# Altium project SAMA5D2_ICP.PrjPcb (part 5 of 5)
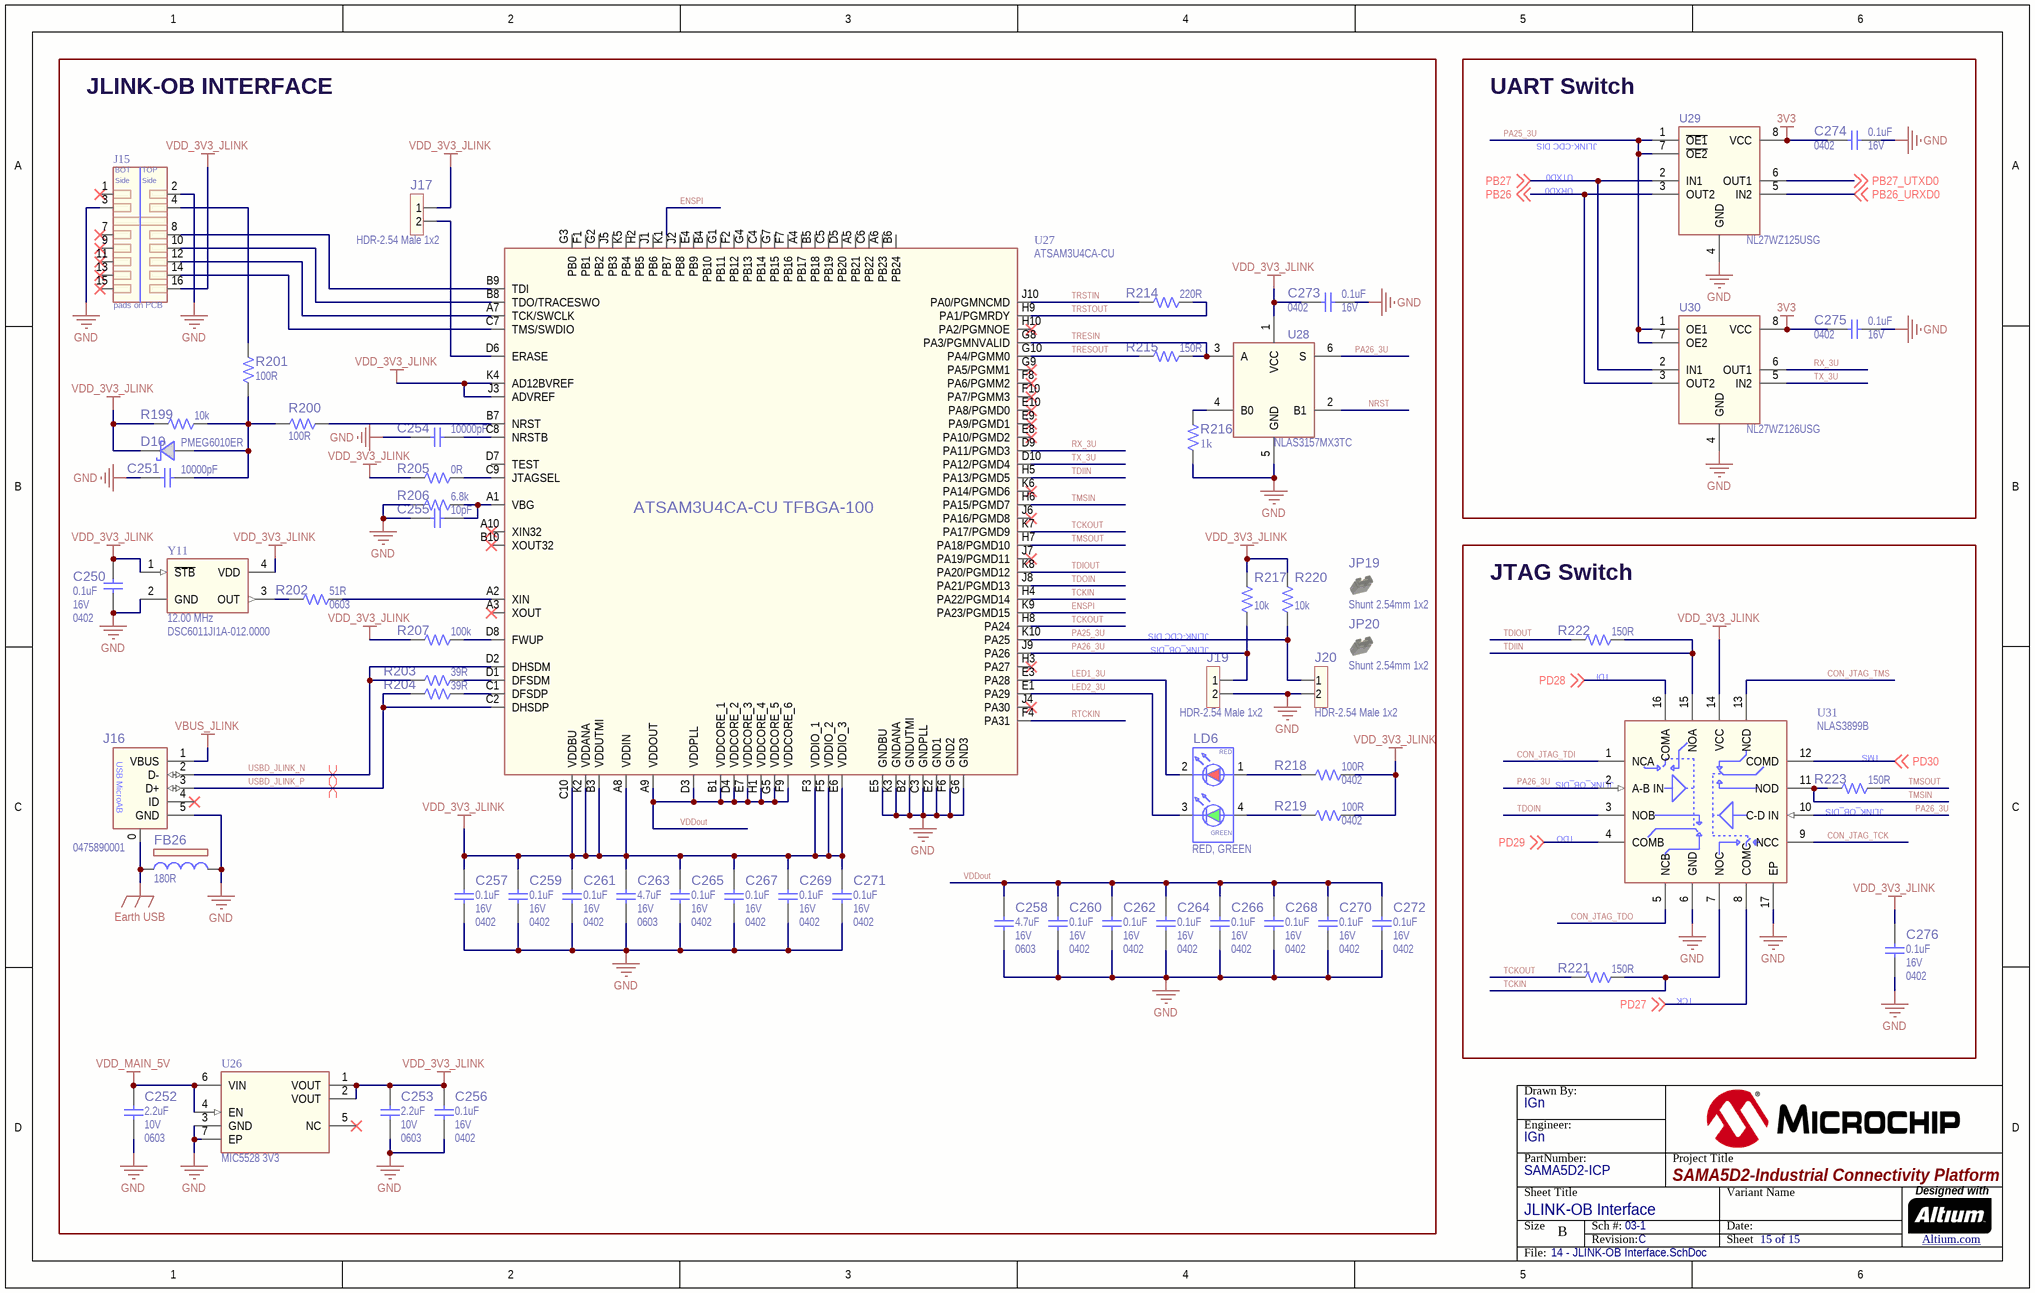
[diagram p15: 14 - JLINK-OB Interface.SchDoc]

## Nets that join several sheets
1V25: 01 - Power Supply (C16.1 L3.2 U2.25), 02 - Power Measurement (FB1.1 FB2.1 R18.1 R19.1), 08 - Ethernet switch (15 pins)
1V35: 01 - Power Supply (C14.1 L2.2 U2.16), 02 - Power Measurement (R17.1)
3V3: 01 - Power Supply (7 pins), 02 - Power Measurement (7 pins), 03 - SAMA5D2 - MPU (C52.2 R166.1 Y3.4), 05 - SAMA5D2 - PIOs (10 pins), 06 - USB (16 pins), 07 - USB HSIC to Gb Ethernet (31 pins), 08 - Ethernet switch (28 pins), 09 - EtherCAT interface (32 pins), 10 - CAN & WiFi BT (12 pins), 11 - On Board Memories (19 pins), 12 - Expansion connectors (R106.1 R229.1 R230.1 R231.1), 13 - User Command & Control (J18.1 R211.2 R212.2 R213.2), 14 - JLINK-OB Interface (C274.2 C275.2 U29.8 U30.8)
Earth USB: 06 - USB (FB14.2 J7.0 J8.0 J9.0), 14 - JLINK-OB Interface (FB26.1 J16.0)
GND: 01 - Power Supply (37 pins), 02 - Power Measurement (9 pins), 03 - SAMA5D2 - MPU (79 pins), 04 - SAMA5D2 - DDR (93 pins), 05 - SAMA5D2 - PIOs (C58.1 C59.1 U35.2 U36.2), 06 - USB (51 pins), 07 - USB HSIC to Gb Ethernet (37 pins), 08 - Ethernet switch (56 pins), 09 - EtherCAT interface (68 pins), 10 - CAN & WiFi BT (39 pins), 11 - On Board Memories (15 pins), 12 - Expansion connectors (11 pins), 13 - User Command & Control (20 pins), 14 - JLINK-OB Interface (50 pins)
VBUS_JLINK: 01 - Power Supply (C4.2 Q2.1 R11.1), 14 - JLINK-OB Interface (J16.1)
VDD_LED: 01 - Power Supply (C10.2 U2.21), 13 - User Command & Control (LD7.2)
VDD_MAIN_5V: 01 - Power Supply (20 pins), 02 - Power Measurement (C22.2 C24.2 U3.A4), 06 - USB (C144.1 C145.1 U16.7 U17.7), 10 - CAN & WiFi BT (7 pins), 12 - Expansion connectors (R236.1 R237.1 R238.1), 14 - JLINK-OB Interface (C252.2 U26.4 U26.6)
VDDANA: 02 - Power Measurement (FB8.2), 03 - SAMA5D2 - MPU (5 pins)
VDDAUDIOPLL: 02 - Power Measurement (L7.2), 03 - SAMA5D2 - MPU (C57.2 C61.2 U4.T3)
VDDBU: 01 - Power Supply (J2.1 R256.2), 03 - SAMA5D2 - MPU (C56.2 R75.1 U4.N7)
VDDCORE: 02 - Power Measurement (R18.2), 03 - SAMA5D2 - MPU (14 pins)
VDDFUSE: 01 - Power Supply (C9.2 U2.19), 03 - SAMA5D2 - MPU (C55.2 U4.M12)
VDDHSIC: 02 - Power Measurement (FB2.2), 03 - SAMA5D2 - MPU (C47.2 U4.R9)
VDDIODDR: 02 - Power Measurement (C23.2 C25.2 R17.2 R25.2), 03 - SAMA5D2 - MPU (15 pins), 04 - SAMA5D2 - DDR (81 pins)
VDDIOP0: 02 - Power Measurement (FB3.2), 03 - SAMA5D2 - MPU (C37.2 C41.2 U4.E6 U4.F7)
VDDIOP1: 02 - Power Measurement (FB4.2), 03 - SAMA5D2 - MPU (C46.2 C50.2 U4.N13 U4.R14)
VDDIOP2: 02 - Power Measurement (FB5.2), 03 - SAMA5D2 - MPU (C38.2 U4.F10)
VDDISC: 02 - Power Measurement (FB6.2), 03 - SAMA5D2 - MPU (C73.2 U4.F4)
VDDOSC: 02 - Power Measurement (L6.2), 03 - SAMA5D2 - MPU (C71.2 C72.2 U4.T7)
VDDPLLA: 02 - Power Measurement (L5.2), 03 - SAMA5D2 - MPU (C69.2 C70.2 U4.U4)
VDDSDHC: 02 - Power Measurement (FB9.2), 03 - SAMA5D2 - MPU (C66.2 U4.P11)
VDDUTMIC: 02 - Power Measurement (FB1.2), 03 - SAMA5D2 - MPU (C62.2 C65.2 U4.P7)
VDDUTMII: 02 - Power Measurement (FB7.2), 03 - SAMA5D2 - MPU (C64.2 U4.P8)
CON_JTAG_TCK: 13 - User Command & Control (J18.4 R212.1), 14 - JLINK-OB Interface (U31.9)
CON_JTAG_TDI: 13 - User Command & Control (J18.8 R213.1), 14 - JLINK-OB Interface (U31.1)
CON_JTAG_TDO: 13 - User Command & Control (J18.6), 14 - JLINK-OB Interface (U31.5)
CON_JTAG_TMS: 13 - User Command & Control (J18.2 R211.1), 14 - JLINK-OB Interface (U31.13)
DDR_REF: 02 - Power Measurement (C25.1 C26.2 R25.1 R26.2), 04 - SAMA5D2 - DDR (11 pins)
DIS_BOOT: 11 - On Board Memories (R80.1 U5.1), 13 - User Command & Control (R251.1)
HHSA_n: 03 - SAMA5D2 - MPU (U4.R8), 06 - USB (J9.2)
HHSA_p: 03 - SAMA5D2 - MPU (U4.T8), 06 - USB (J9.3)
HHSB_n: 03 - SAMA5D2 - MPU (U4.U9), 06 - USB (U15.30)
HHSB_p: 03 - SAMA5D2 - MPU (U4.U8), 06 - USB (U15.31)
HSIC_DATA: 03 - SAMA5D2 - MPU (U4.T9), 07 - USB HSIC to Gb Ethernet (U19.38)
HSIC_STROBE: 03 - SAMA5D2 - MPU (U4.U10), 07 - USB HSIC to Gb Ethernet (U19.35)
NRST: 01 - Power Supply (R2.1 U2.2), 03 - SAMA5D2 - MPU (U4.U2), 06 - USB (U12.2), 07 - USB HSIC to Gb Ethernet (U18.2), 08 - Ethernet switch (U20.2), 09 - EtherCAT interface (U22.2), 13 - User Command & Control (R210.2 R250.1), 14 - JLINK-OB Interface (U28.2)
NSTART: 01 - Power Supply (C2.2 U2.24), 13 - User Command & Control (R252.1)
PA0: 05 - SAMA5D2 - PIOs (U4.U11), 12 - Expansion connectors (J5.5)
PA1: 05 - SAMA5D2 - PIOs (U4.P10), 12 - Expansion connectors (J5.2 R104.1)
PA2: 05 - SAMA5D2 - PIOs (U4.T11), 12 - Expansion connectors (J5.7 R101.7)
PA3: 05 - SAMA5D2 - PIOs (U4.R10), 12 - Expansion connectors (J5.8 R101.6)
PA4: 05 - SAMA5D2 - PIOs (U4.U12), 12 - Expansion connectors (J5.9 R101.5)
PA5: 05 - SAMA5D2 - PIOs (U4.T12), 12 - Expansion connectors (J5.1 R101.8)
PA6_SCK: 05 - SAMA5D2 - PIOs (R31.2), 11 - On Board Memories (U7.6)
PA6_TXD: 05 - SAMA5D2 - PIOs (R32.2), 10 - CAN & WiFi BT (U32.9)
PA7_IO0: 05 - SAMA5D2 - PIOs (R33.2), 11 - On Board Memories (U7.5)
PA7_RXD: 05 - SAMA5D2 - PIOs (R34.2), 10 - CAN & WiFi BT (U32.8)
PA8_IO1: 05 - SAMA5D2 - PIOs (R35.2), 11 - On Board Memories (U7.2)
PA8_W3K_RST: 05 - SAMA5D2 - PIOs (R36.2), 10 - CAN & WiFi BT (U32.7)
PA9_CTS: 05 - SAMA5D2 - PIOs (R38.2), 10 - CAN & WiFi BT (U32.10)
PA9_IO2: 05 - SAMA5D2 - PIOs (R37.2), 11 - On Board Memories (R84.1 U7.3)
PA10_IO3: 05 - SAMA5D2 - PIOs (R39.2), 11 - On Board Memories (R88.1 U7.7)
PA10_RTS: 05 - SAMA5D2 - PIOs (R40.2), 10 - CAN & WiFi BT (U32.11)
PA11_CS: 05 - SAMA5D2 - PIOs (R41.2), 11 - On Board Memories (U5.2)
PA12: 05 - SAMA5D2 - PIOs (U4.N15), 12 - Expansion connectors (J5.11 R102.1)
PA13: 05 - SAMA5D2 - PIOs (U4.P16), 12 - Expansion connectors (J5.10 R103.1)
PA14: 05 - SAMA5D2 - PIOs (U4.M14), 12 - Expansion connectors (J23.4)
PA15: 05 - SAMA5D2 - PIOs (U4.N16), 12 - Expansion connectors (J23.6)
PA16: 05 - SAMA5D2 - PIOs (U4.M10), 12 - Expansion connectors (J23.5)
PA17: 05 - SAMA5D2 - PIOs (U4.N17), 12 - Expansion connectors (J23.3)
PA18: 05 - SAMA5D2 - PIOs (U4.U14), 10 - CAN & WiFi BT (U32.24)
PA19: 05 - SAMA5D2 - PIOs (U4.T14), 10 - CAN & WiFi BT (U32.25)
PA20: 05 - SAMA5D2 - PIOs (U4.P12), 10 - CAN & WiFi BT (U32.26)
PA21: 05 - SAMA5D2 - PIOs (U4.R13), 10 - CAN & WiFi BT (U32.27)
PA22_CK: 05 - SAMA5D2 - PIOs (R27.2), 10 - CAN & WiFi BT (U32.22)
PA22_D0: 05 - SAMA5D2 - PIOs (R28.2), 09 - EtherCAT interface (U24.17)
PA23: 05 - SAMA5D2 - PIOs (U4.U16), 09 - EtherCAT interface (U24.13)
PA24: 05 - SAMA5D2 - PIOs (U4.T15), 09 - EtherCAT interface (U24.12)
PA25: 05 - SAMA5D2 - PIOs (U4.U17), 09 - EtherCAT interface (U24.35)
PA26: 05 - SAMA5D2 - PIOs (U4.P13), 09 - EtherCAT interface (U24.49)
PA27: 05 - SAMA5D2 - PIOs (U4.T16), 09 - EtherCAT interface (U24.50)
PA28_CMD: 05 - SAMA5D2 - PIOs (R29.2), 10 - CAN & WiFi BT (U32.23)
PA28_D6: 05 - SAMA5D2 - PIOs (R30.2), 09 - EtherCAT interface (U24.36)
PA29: 05 - SAMA5D2 - PIOs (U4.T17), 09 - EtherCAT interface (U24.39)
PA30: 05 - SAMA5D2 - PIOs (U4.R15), 09 - EtherCAT interface (U24.30)
PA31: 05 - SAMA5D2 - PIOs (U4.R17), 13 - User Command & Control (R239.1 R242.2)
PB0: 05 - SAMA5D2 - PIOs (U4.J8), 13 - User Command & Control (R241.1)
PB1: 05 - SAMA5D2 - PIOs (U4.A8), 13 - User Command & Control (R240.1 R243.2)
PB2: 05 - SAMA5D2 - PIOs (U4.A7), 09 - EtherCAT interface (U24.31)
PB3: 05 - SAMA5D2 - PIOs (U4.A6), 09 - EtherCAT interface (U24.40)
PB4: 05 - SAMA5D2 - PIOs (U4.B6), 09 - EtherCAT interface (U24.19)
PB5: 05 - SAMA5D2 - PIOs (U4.B7), 09 - EtherCAT interface (U24.23)
PB6: 05 - SAMA5D2 - PIOs (U4.C7), 09 - EtherCAT interface (U24.22)
PB7: 05 - SAMA5D2 - PIOs (U4.C6), 09 - EtherCAT interface (U24.21)
PB8: 05 - SAMA5D2 - PIOs (U4.A5), 09 - EtherCAT interface (U24.16)
PB9: 05 - SAMA5D2 - PIOs (U4.A4), 09 - EtherCAT interface (U24.15)
PB10: 05 - SAMA5D2 - PIOs (U4.H8), 09 - EtherCAT interface (U24.33)
PB11: 05 - SAMA5D2 - PIOs (U4.B5), 09 - EtherCAT interface (R171.1 U24.44)
PB12: 05 - SAMA5D2 - PIOs (U4.D6), 09 - EtherCAT interface (U24.25)
PB13: 05 - SAMA5D2 - PIOs (U4.B4), 09 - EtherCAT interface (U24.29)
PB14: 05 - SAMA5D2 - PIOs (U4.C5), 09 - EtherCAT interface (U24.26)
PB15: 05 - SAMA5D2 - PIOs (U4.H7), 09 - EtherCAT interface (U24.27)
PB16: 05 - SAMA5D2 - PIOs (U4.D5), 09 - EtherCAT interface (U22.1)
PB17: 02 - Power Measurement (R24.1 U3.C3), 05 - SAMA5D2 - PIOs (U4.C4)
PB18: 01 - Power Supply (R1.1 U2.1), 05 - SAMA5D2 - PIOs (U4.A3)
PB19: 05 - SAMA5D2 - PIOs (U4.D4), 12 - Expansion connectors (J23.15)
PB20: 05 - SAMA5D2 - PIOs (U4.B3), 12 - Expansion connectors (J23.16)
PB21: 05 - SAMA5D2 - PIOs (U4.A2), 12 - Expansion connectors (J23.2)
PB22: 05 - SAMA5D2 - PIOs (U4.C3), 12 - Expansion connectors (J22.15)
PB23: 05 - SAMA5D2 - PIOs (U4.A1), 12 - Expansion connectors (J22.16)
PB24: 05 - SAMA5D2 - PIOs (U4.E5), 12 - Expansion connectors (J22.2)
PB25: 05 - SAMA5D2 - PIOs (U4.B2), 10 - CAN & WiFi BT (R107.1 U13.8 U14.8)
PB26: 05 - SAMA5D2 - PIOs (U4.E4), 14 - JLINK-OB Interface (U29.3 U30.3)
PB26_URXD0: 12 - Expansion connectors (J21.14), 14 - JLINK-OB Interface (U29.5)
PB27: 05 - SAMA5D2 - PIOs (U4.B1), 14 - JLINK-OB Interface (U29.2 U30.2)
PB27_UTXD0: 12 - Expansion connectors (J21.13), 14 - JLINK-OB Interface (U29.6)
PB28: 05 - SAMA5D2 - PIOs (U4.C2), 08 - Ethernet switch (U21.49), 12 - Expansion connectors (J22.6)
PB29: 05 - SAMA5D2 - PIOs (U4.D3), 08 - Ethernet switch (U21.48), 12 - Expansion connectors (J22.5)
PB30: 05 - SAMA5D2 - PIOs (U4.D2), 08 - Ethernet switch (U21.53), 12 - Expansion connectors (J22.4)
PB31: 05 - SAMA5D2 - PIOs (U4.C1), 12 - Expansion connectors (J22.3)
PC0: 05 - SAMA5D2 - PIOs (U4.P17), 08 - Ethernet switch (U21.52)
PC1: 05 - SAMA5D2 - PIOs (U4.N12), 07 - USB HSIC to Gb Ethernet (U19.29)
PC2: 05 - SAMA5D2 - PIOs (U4.N14), 07 - USB HSIC to Gb Ethernet (R268.1 U18.1)
PC3: 05 - SAMA5D2 - PIOs (U4.M15), 12 - Expansion connectors (J21.15)
PC4: 05 - SAMA5D2 - PIOs (U4.M11), 12 - Expansion connectors (J21.16)
PC5: 05 - SAMA5D2 - PIOs (U4.L10), 12 - Expansion connectors (J21.2)
PC6: 05 - SAMA5D2 - PIOs (U4.K10), 09 - EtherCAT interface (U23.2)
PC7: 05 - SAMA5D2 - PIOs (U4.M16), 12 - Expansion connectors (J23.14)
PC8: 05 - SAMA5D2 - PIOs (U4.J10), 12 - Expansion connectors (J23.13)
PC9: 05 - SAMA5D2 - PIOs (U4.D1), 13 - User Command & Control (R227.2)
PC10: 05 - SAMA5D2 - PIOs (U4.E3), 10 - CAN & WiFi BT (U13.1)
PC11: 05 - SAMA5D2 - PIOs (U4.E2), 10 - CAN & WiFi BT (C124.2 U13.4)
PC12: 05 - SAMA5D2 - PIOs (U4.E1), 12 - Expansion connectors (J22.14)
PC13: 05 - SAMA5D2 - PIOs (U4.F3), 12 - Expansion connectors (J22.13)
PC14: 05 - SAMA5D2 - PIOs (U4.F5), 10 - CAN & WiFi BT (R249.1 U32.33)
PC15: 05 - SAMA5D2 - PIOs (U4.F2 U35.6 U36.6), 09 - EtherCAT interface (U23.1), 10 - CAN & WiFi BT (R271.2 U37.3)
PC16: 05 - SAMA5D2 - PIOs (U4.G6), 08 - Ethernet switch (R153.2 U21.45)
PC17: 05 - SAMA5D2 - PIOs (U4.F1), 06 - USB (U12.1)
PC18: 05 - SAMA5D2 - PIOs (U4.H6), 12 - Expansion connectors (J21.4)
PC19: 05 - SAMA5D2 - PIOs (U4.G2), 12 - Expansion connectors (J21.5)
PC20: 05 - SAMA5D2 - PIOs (U4.G3), 12 - Expansion connectors (J21.6)
PC21: 05 - SAMA5D2 - PIOs (U4.G1), 12 - Expansion connectors (J21.3)
PC22: 05 - SAMA5D2 - PIOs (U4.H2), 07 - USB HSIC to Gb Ethernet (R131.1 U19.27)
PC23: 05 - SAMA5D2 - PIOs (U4.G5), 07 - USB HSIC to Gb Ethernet (U19.39)
PC24: 05 - SAMA5D2 - PIOs (U4.H1), 07 - USB HSIC to Gb Ethernet (U19.32)
PC25: 05 - SAMA5D2 - PIOs (U4.H5), 13 - User Command & Control (R235.1)
PC26: 05 - SAMA5D2 - PIOs (U4.J9), 10 - CAN & WiFi BT (U14.1)
PC27: 05 - SAMA5D2 - PIOs (U4.H9), 10 - CAN & WiFi BT (C125.2 U14.4)
PC28_MCP16502: 01 - Power Supply (U2.5), 05 - SAMA5D2 - PIOs (R60.2)
PC28_PAC1934: 02 - Power Measurement (U3.D4), 05 - SAMA5D2 - PIOs (R61.2)
PC29_MCP16502: 01 - Power Supply (U2.6), 05 - SAMA5D2 - PIOs (R62.2)
PC29_PAC1934: 02 - Power Measurement (U3.C4), 05 - SAMA5D2 - PIOs (R63.2)
PC30: 05 - SAMA5D2 - PIOs (U4.F8), 13 - User Command & Control (R234.2)
PC31: 01 - Power Supply (U2.23), 05 - SAMA5D2 - PIOs (U4.D8)
PD0: 05 - SAMA5D2 - PIOs (U4.G10), 13 - User Command & Control (R254.1)
PD1: 05 - SAMA5D2 - PIOs (U4.E10), 08 - Ethernet switch (U21.22)
PD2: 05 - SAMA5D2 - PIOs (U4.G9), 08 - Ethernet switch (U21.33)
PD3: 05 - SAMA5D2 - PIOs (U4.K1), 08 - Ethernet switch (R177.1 U21.46)
PD4: 05 - SAMA5D2 - PIOs (U4.J6), 08 - Ethernet switch (U20.1)
PD5: 05 - SAMA5D2 - PIOs (U4.J4), 08 - Ethernet switch (R157.1 U21.19)
PD6: 05 - SAMA5D2 - PIOs (U4.J2), 08 - Ethernet switch (R266.1 U21.18)
PD7: 05 - SAMA5D2 - PIOs (U4.J7), 08 - Ethernet switch (U21.27)
PD8: 05 - SAMA5D2 - PIOs (U4.J1), 08 - Ethernet switch (U21.26)
PD9: 05 - SAMA5D2 - PIOs (U4.K9), 08 - Ethernet switch (U21.30)
PD10: 05 - SAMA5D2 - PIOs (U4.J3), 08 - Ethernet switch (U21.32)
PD11: 05 - SAMA5D2 - PIOs (U4.M1), 08 - Ethernet switch (R259.1 U21.24)
PD12: 05 - SAMA5D2 - PIOs (U4.K8), 08 - Ethernet switch (R267.1 U21.25)
PD13: 05 - SAMA5D2 - PIOs (U4.L2), 08 - Ethernet switch (R155.1 U21.21)
PD14: 05 - SAMA5D2 - PIOs (U4.K4), 08 - Ethernet switch (R156.2 U21.20)
PD15: 05 - SAMA5D2 - PIOs (U4.K7), 08 - Ethernet switch (U21.29)
PD16: 05 - SAMA5D2 - PIOs (U4.L1), 08 - Ethernet switch (U21.28)
PD19_ECC608: 05 - SAMA5D2 - PIOs (R269.2), 11 - On Board Memories (U34.5)
PD19_EEPROM1: 05 - SAMA5D2 - PIOs (R48.2), 11 - On Board Memories (U9.3)
PD19_EEPROM2: 05 - SAMA5D2 - PIOs (R49.2), 11 - On Board Memories (U10.3)
PD19_EEPROM3: 05 - SAMA5D2 - PIOs (R50.2), 11 - On Board Memories (U11.3)
PD20_ECC608: 05 - SAMA5D2 - PIOs (R270.2), 11 - On Board Memories (U34.6)
PD20_EEPROM1: 05 - SAMA5D2 - PIOs (R51.2), 11 - On Board Memories (U9.1)
PD20_EEPROM2: 05 - SAMA5D2 - PIOs (R52.2), 11 - On Board Memories (U10.1)
PD20_EEPROM3: 05 - SAMA5D2 - PIOs (R53.2), 11 - On Board Memories (U11.1)
PD21_MKBUS1: 05 - SAMA5D2 - PIOs (R54.2), 12 - Expansion connectors (J21.11)
PD21_MKBUS2: 05 - SAMA5D2 - PIOs (R55.2), 12 - Expansion connectors (J22.11)
PD21_MKBUS3: 05 - SAMA5D2 - PIOs (R56.2), 12 - Expansion connectors (J23.11)
PD22_MKBUS1: 05 - SAMA5D2 - PIOs (R57.2), 12 - Expansion connectors (J21.12)
PD22_MKBUS2: 05 - SAMA5D2 - PIOs (R58.2), 12 - Expansion connectors (J22.12)
PD22_MKBUS3: 05 - SAMA5D2 - PIOs (R59.2), 12 - Expansion connectors (J23.12)
PD23: 05 - SAMA5D2 - PIOs (U4.M3), 06 - USB (R129.2 R130.1)
PD24: 05 - SAMA5D2 - PIOs (U4.L7), 12 - Expansion connectors (J23.1)
PD25: 05 - SAMA5D2 - PIOs (U4.L6), 12 - Expansion connectors (J22.1)
PD26: 05 - SAMA5D2 - PIOs (U4.N2), 12 - Expansion connectors (J21.1)
PD27: 05 - SAMA5D2 - PIOs (U4.L8), 14 - JLINK-OB Interface (U31.8)
PD28: 05 - SAMA5D2 - PIOs (U4.M4), 14 - JLINK-OB Interface (U31.16)
PD29: 05 - SAMA5D2 - PIOs (U4.N3), 14 - JLINK-OB Interface (U31.4)
PD30: 05 - SAMA5D2 - PIOs (U4.L9), 14 - JLINK-OB Interface (U31.12)
PD31: 05 - SAMA5D2 - PIOs (U4.M7), 13 - User Command & Control (R228.2)
PIOBU1: 03 - SAMA5D2 - MPU (U4.N8), 13 - User Command & Control (R255.2)
PIOBU2: 03 - SAMA5D2 - MPU (U4.R2), 13 - User Command & Control (R224.1)
PIOBU3: 03 - SAMA5D2 - MPU (U4.R5), 13 - User Command & Control (R232.2)
PIOBU4: 03 - SAMA5D2 - MPU (U4.R4), 13 - User Command & Control (R225.1)
PIOBU5: 03 - SAMA5D2 - MPU (U4.P5), 13 - User Command & Control (R233.2)
PIOBU6: 03 - SAMA5D2 - MPU (U4.P6), 13 - User Command & Control (R226.1)
PIOBU7: 01 - Power Supply (Q6.1), 03 - SAMA5D2 - MPU (U4.M8)
RTCKIN: 13 - User Command & Control (R208.2 R209.2), 14 - JLINK-OB Interface (U27.F4)
SHDN: 01 - Power Supply (R6.1), 03 - SAMA5D2 - MPU (U4.R1)
WAKE_UP: 01 - Power Supply (R256.1 U2.7), 03 - SAMA5D2 - MPU (U4.P4)

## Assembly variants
Standard: not fitted C60 C67 C140 C141 C183 C189 C222 C229 C300 J3 J4 J17 J24 J25 J26 J27 R7 R8 R9 R10 R70 R71 R75 R87 R95 R111 R114 R115 R146 R147 R166 R169 R170 R205 R209 R268 R271 Y4 Y8 Y10
Standard_WILC3000_DNP: not fitted C60 C67 C140 C141 C183 C189 C222 C229 C300 J3 J4 J17 J24 J25 J26 J27 R7 R8 R9 R10 R70 R71 R75 R87 R95 R111 R114 R115 R146 R147 R166 R169 R170 R205 R209 R268 R271 U32 Y4 Y8 Y10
